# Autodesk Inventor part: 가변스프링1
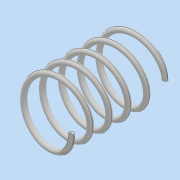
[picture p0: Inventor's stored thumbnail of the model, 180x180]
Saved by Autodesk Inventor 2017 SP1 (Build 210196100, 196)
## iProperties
Part Number: 가변스프링1
Material: 일반
Document SubType Name: Modeling
Designer: MRC
Density: 1 g/cm^3
Appearance: 기본값
Mass: 1.07302 g
Surface Area: 21.7217 cm^2
Volume: 1.07302 cm^3
Author: MRC
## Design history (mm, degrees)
sketch "스케치1"
  geometry: L1 (0, 0)-(0, 36.411); L2 (0, 0)-(11, 0); L3 (0, 36.411)-(11, 36.411); C1 r 1 at (11, 0)
  constraints: 6 end point, 2 horizontal, 1 centre point, 1 coincident, 1 vertical
  dimensions: "d0" = 36.4112 distance of L1.start L1.end (derived); "d1" = 2 diameter of C1; "d2" = 22 diameter of L2.end L1
feature "코일1" sketch "스케치1" pitch "d3" = 10; turns "d5" = 5; dims "d4" = 36.4112 (= d0), "d6" = 0, angle "d7" = 90 deg, angle "d8" = 90 deg, "d9" = 0, "d10" = 0
sketch "스케치2"
  geometry: L1 (15, 0)-(-15, 0); L2 (-15, 0)-(-15, 36.411); L3 (-15, 36.411)-(15, 36.411); L4 (15, 36.411)-(15, 0); 1 further point
  constraints: 8 end point, 2 parallel, 1 horizontal, 1 midpoint, 1 perpendicular
  dimensions: "d11" = 36.4112 distance of L3.end L1.start (= d0); "d12" = 30 distance between parallel lines of L2 L4; "d13" = 15 distance from line of point (0, 0) L4 (= 0.5 x d12)
extrude "돌출1" sketch "스케치2" stored distance "d14" = 30; taper "d15" = 0 deg
node "솔리드1"
